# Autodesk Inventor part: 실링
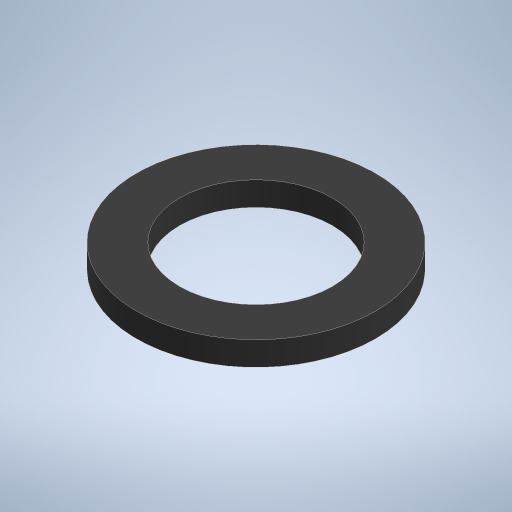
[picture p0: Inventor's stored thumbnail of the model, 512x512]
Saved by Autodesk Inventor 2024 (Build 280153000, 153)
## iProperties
Created: 2024-11
Part Number: 실링
Material: 고무
Document SubType Name: Modeling
Designer: user
Density: 0.93 g/cm^3
Appearance: 기본값
Author: jhkim
Sending System: Autodesk Inventor 2025
Preprocessor: ST-DEVELOPER v20
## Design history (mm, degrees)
node "실링1"
node "솔리드2"
node "솔리드1"
